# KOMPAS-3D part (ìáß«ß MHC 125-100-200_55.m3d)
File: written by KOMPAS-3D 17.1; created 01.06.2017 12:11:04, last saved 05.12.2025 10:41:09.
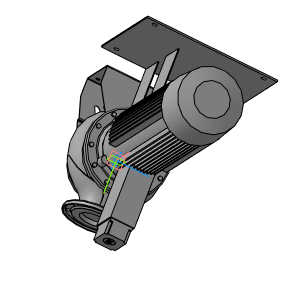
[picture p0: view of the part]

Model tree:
1. Операция без истории:1

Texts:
  ООО АДЛ ГРУПП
